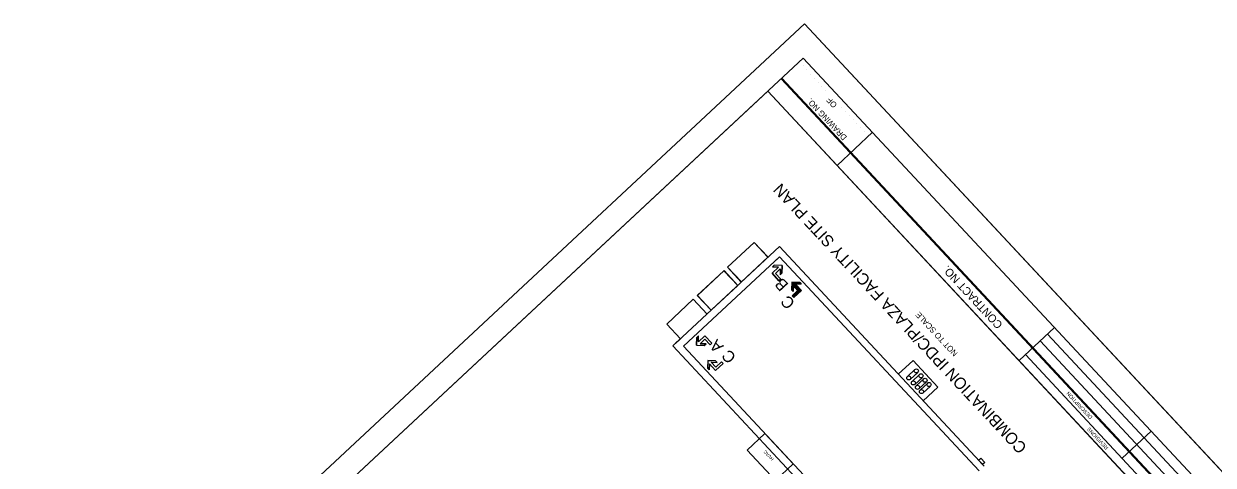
# Model space of a CAD drawing. Extents: x 1121979 to 1130574, y 1838676 to 1848573.
# Drawn here: x 1129608.35 to 1129657.38, y 1839397.19 to 1839415.39 of the extents above; entities that cross this region are included whole.
import ezdxf

# ---------------------------------------------------------------- set-up
doc = ezdxf.new("R2010")
doc.units = 0
for name, color, linetype in [('CLB-6', 7, 'Continuous'), ('Default', 7, 'Continuous'), ('Future by Others', 7, 'Continuous'), ('GE-NOT-Notes', 7, 'Continuous'), ('GE-NOT-Titles', 7, 'Continuous'), ('GE-SHT-Clip Border', 7, 'Continuous'), ('GE-SHT-General', 7, 'Continuous'), ('GE-SHT-Plot Border', 7, 'Continuous'), ('HS_Dimensions and Text', 7, 'Continuous'), ('IPDC BUILDING RELATED', 7, 'Continuous'), ('IPDC ELECT ITS RELATED', 7, 'Continuous'), ('IPDC-EXIST ELECT EQUIP', 7, 'Continuous'), ('IT-PCM-Proposed Communications Conduit', 7, 'Continuous'), ('Sheets_General Details', 7, 'Continuous'), ('Sheets_Printer Plotting Border', 7, 'Continuous')]:
    doc.layers.add(name, color=color, linetype=linetype)

msp = doc.modelspace()

# ---------------------------------------------------------------- linework, layer by layer
at = {"layer": 'CLB-6'}
for p, q in [((1129635.85, 1839401.766), (1129635.839, 1839401.777)), ((1129636.186, 1839401.406), (1129636.175, 1839401.417))]:
    msp.add_line(p, q, dxfattribs=at)
at = {"layer": 'Default'}
for p, q in [((1129635.22, 1839402.222), (1129635.389, 1839402.381)), ((1129635.223, 1839402.214), (1129635.395, 1839402.375)), ((1129635.389, 1839402.381), (1129635.395, 1839402.375))]:
    msp.add_line(p, q, dxfattribs=at)
at = {"layer": 'Future by Others'}
msp.add_lwpolyline([(1129647.873, 1839397.217), (1129647.703, 1839397.399), (1129647.794, 1839397.485), (1129647.964, 1839397.302)], close=True, dxfattribs=at)
at = {"layer": 'GE-NOT-Notes'}
for p, q in [((1129686.907, 1839365.651), (1129640.533, 1839415.386)), ((1129639.194, 1839405.101), (1129639.464, 1839405.353)), ((1129639.288, 1839405.43), (1129639.215, 1839405.362)), ((1129639.464, 1839405.353), (1129639.215, 1839405.362)), ((1129639.608, 1839405.419), (1129639.288, 1839405.43)), ((1129639.335, 1839405.096), (1129639.532, 1839405.28)), ((1129639.532, 1839405.28), (1129639.524, 1839405.031)), ((1129639.608, 1839405.419), (1129639.597, 1839405.1)), ((1129639.48, 1839404.794), (1129639.194, 1839405.101)), ((1129639.553, 1839404.862), (1129639.335, 1839405.096)), ((1129639.553, 1839404.862), (1129639.48, 1839404.794)), ((1129639.597, 1839405.1), (1129639.524, 1839405.031)), ((1129640.013, 1839404.737), (1129640.002, 1839404.417)), ((1129640.013, 1839404.737), (1129640.333, 1839404.726)), ((1129640.404, 1839404.391), (1129640.152, 1839404.661)), ((1129640.152, 1839404.661), (1129640.401, 1839404.652)), ((1129640.333, 1839404.726), (1129640.401, 1839404.652)), ((1129640.002, 1839404.417), (1129640.07, 1839404.344)), ((1129640.029, 1839404.178), (1129640.263, 1839404.396)), ((1129640.029, 1839404.178), (1129640.097, 1839404.104)), ((1129640.079, 1839404.593), (1129640.07, 1839404.344)), ((1129640.263, 1839404.396), (1129640.079, 1839404.593)), ((1129640.097, 1839404.104), (1129640.404, 1839404.391)), ((1129636.084, 1839402.133), (1129636.095, 1839402.453)), ((1129636.095, 1839402.453), (1129636.168, 1839402.521)), ((1129636.43, 1839402.524), (1129636.159, 1839402.272)), ((1129636.159, 1839402.272), (1129636.168, 1839402.521)), ((1129636.425, 1839402.383), (1129636.228, 1839402.199)), ((1129636.228, 1839402.199), (1129636.476, 1839402.19)), ((1129636.403, 1839402.122), (1129636.476, 1839402.19)), ((1129636.643, 1839402.149), (1129636.425, 1839402.383)), ((1129636.716, 1839402.217), (1129636.43, 1839402.524)), ((1129636.643, 1839402.149), (1129636.716, 1839402.217)), ((1129636.084, 1839402.133), (1129636.403, 1839402.122)), ((1129636.55, 1839401.508), (1129636.539, 1839401.188)), ((1129636.55, 1839401.508), (1129636.869, 1839401.496)), ((1129636.616, 1839401.364), (1129636.607, 1839401.115)), ((1129636.868, 1839401.093), (1129636.616, 1839401.364)), ((1129636.873, 1839401.235), (1129636.689, 1839401.432)), ((1129636.689, 1839401.432), (1129636.938, 1839401.423)), ((1129637.175, 1839401.38), (1129636.868, 1839401.093)), ((1129636.869, 1839401.496), (1129636.938, 1839401.423)), ((1129637.107, 1839401.453), (1129636.873, 1839401.235)), ((1129637.107, 1839401.453), (1129637.175, 1839401.38)), ((1129636.539, 1839401.188), (1129636.607, 1839401.115))]:
    msp.add_line(p, q, dxfattribs=at)
at = {"layer": 'GE-SHT-Clip Border'}
msp.add_lwpolyline([(1129652.729, 1839339.252), (1129609.766, 1839385.33), (1129639.021, 1839412.608), (1129681.985, 1839366.531)], close=True, dxfattribs=at)
msp.add_lwpolyline([(1129652.729, 1839339.252), (1129609.766, 1839385.33), (1129639.021, 1839412.608), (1129681.985, 1839366.531)], close=True, dxfattribs=at)
msp.add_lwpolyline([(1129652.729, 1839339.252), (1129609.766, 1839385.33), (1129639.021, 1839412.608), (1129681.985, 1839366.531)], close=True, dxfattribs=at)
at = {"layer": 'GE-SHT-General'}
for p, q in [((1129640.484, 1839413.972), (1129640.484, 1839413.972)), ((1129640.475, 1839413.647), (1129640.475, 1839413.647)), ((1129640.63, 1839413.481), (1129640.63, 1839413.481)), ((1129656.061, 1839395.434), (1129639.57, 1839413.12)), ((1129656.092, 1839395.463), (1129639.601, 1839413.149)), ((1129640.784, 1839413.315), (1129640.784, 1839413.315)), ((1129640.939, 1839413.149), (1129640.939, 1839413.149)), ((1129641.094, 1839412.984), (1129641.094, 1839412.984)), ((1129639.021, 1839412.608), (1129681.985, 1839366.531)), ((1129641.248, 1839412.818), (1129641.248, 1839412.818)), ((1129641.403, 1839412.652), (1129641.403, 1839412.652)), ((1129642.077, 1839411.929), (1129642.077, 1839411.929)), ((1129642.231, 1839411.764), (1129642.231, 1839411.764)), ((1129642.386, 1839411.598), (1129642.386, 1839411.598)), ((1129642.54, 1839411.432), (1129642.54, 1839411.432)), ((1129642.695, 1839411.266), (1129642.695, 1839411.266)), ((1129642.849, 1839411.101), (1129642.849, 1839411.101)), ((1129643.336, 1839410.914), (1129641.873, 1839409.55)), ((1129643.004, 1839410.935), (1129643.004, 1839410.935)), ((1129650.837, 1839402.869), (1129649.374, 1839401.505)), ((1129656.387, 1839395.738), (1129650.249, 1839402.321)), ((1129656.682, 1839396.013), (1129650.544, 1839402.596)), ((1129649.638, 1839401.75), (1129655.775, 1839395.168)), ((1129654.824, 1839398.593), (1129653.624, 1839397.475))]:
    msp.add_line(p, q, dxfattribs=at)
msp.add_lwpolyline([(1129652.729, 1839339.252), (1129609.766, 1839385.33), (1129640.484, 1839413.972), (1129683.448, 1839367.895)], close=True, dxfattribs=at)
at = {"layer": 'GE-SHT-Plot Border'}
msp.add_lwpolyline([(1129686.907, 1839365.651), (1129640.533, 1839415.386), (1129608.352, 1839385.379), (1129654.726, 1839335.645)], close=True, dxfattribs=at)
at = {"layer": 'IPDC BUILDING RELATED'}
for points in [[(1129639.497, 1839406.199), (1129635.108, 1839402.107)], [(1129639.497, 1839406.199), (1129647.94, 1839397.144)], [(1129639.507, 1839405.781), (1129635.548, 1839402.09)], [(1129639.507, 1839405.781), (1129639.231, 1839405.524)], [(1129647.737, 1839396.955), (1129639.507, 1839405.781)], [(1129635.108, 1839402.107), (1129648.066, 1839388.211), (1129652.454, 1839392.303), (1129652.117, 1839392.664)], [(1129652.084, 1839392.292), (1129648.126, 1839388.601), (1129635.548, 1839402.09)]]:
    msp.add_lwpolyline(points, dxfattribs=at)
msp.add_lwpolyline([(1129638.899, 1839398.497), (1129638.167, 1839397.815), (1129639.34, 1839396.558), (1129640.071, 1839397.24)], close=True, dxfattribs=at)
at = {"layer": 'IPDC ELECT ITS RELATED'}
for p, q in [((1129637.365, 1839405.352), (1129638.463, 1839406.375)), ((1129639.031, 1839405.765), (1129638.463, 1839406.375)), ((1129636.119, 1839404.189), (1129637.216, 1839405.212)), ((1129637.784, 1839404.603), (1129637.216, 1839405.212)), ((1129637.934, 1839404.742), (1129637.365, 1839405.352)), ((1129636.687, 1839403.58), (1129636.119, 1839404.189)), ((1129634.852, 1839403.008), (1129635.949, 1839404.031)), ((1129636.517, 1839403.421), (1129635.949, 1839404.031)), ((1129635.42, 1839402.398), (1129634.852, 1839403.008))]:
    msp.add_line(p, q, dxfattribs=at)
at = {"layer": 'IPDC-EXIST ELECT EQUIP'}
for p, q in [((1129638.457, 1839406.369), (1129637.36, 1839405.347)), ((1129639.026, 1839405.76), (1129638.457, 1839406.369)), ((1129639.026, 1839405.76), (1129637.928, 1839404.737)), ((1129637.211, 1839405.207), (1129636.113, 1839404.184)), ((1129637.779, 1839404.597), (1129637.211, 1839405.207)), ((1129637.928, 1839404.737), (1129637.36, 1839405.347)), ((1129636.682, 1839403.575), (1129636.113, 1839404.184)), ((1129637.779, 1839404.597), (1129636.682, 1839403.575)), ((1129644.396, 1839400.938), (1129645.005, 1839401.506)), ((1129646.028, 1839400.409), (1129645.005, 1839401.506)), ((1129645.419, 1839399.841), (1129646.028, 1839400.409))]:
    msp.add_line(p, q, dxfattribs=at)
at = {"layer": 'IT-PCM-Proposed Communications Conduit'}
for p, q in [((1129644.773, 1839400.847), (1129645.085, 1839401.138)), ((1129644.887, 1839400.725), (1129645.199, 1839401.016)), ((1129644.964, 1839400.643), (1129645.276, 1839400.934)), ((1129645.078, 1839400.52), (1129645.39, 1839400.811)), ((1129645.134, 1839400.46), (1129645.446, 1839400.752)), ((1129645.248, 1839400.338), (1129645.56, 1839400.629)), ((1129645.297, 1839400.285), (1129645.609, 1839400.576)), ((1129645.411, 1839400.163), (1129645.723, 1839400.454))]:
    msp.add_line(p, q, dxfattribs=at)
for centre in [(1129644.83, 1839400.786), (1129645.142, 1839401.077), (1129645.333, 1839400.873), (1129645.503, 1839400.69), (1129645.021, 1839400.582), (1129645.191, 1839400.399), (1129645.354, 1839400.224), (1129645.666, 1839400.515)]:
    msp.add_circle(centre, 0.0836, dxfattribs=at)
at = {"layer": 'Sheets_General Details'}
for p, q in [((1129639.464, 1839405.353), (1129639.194, 1839405.101)), ((1129639.288, 1839405.43), (1129639.215, 1839405.362)), ((1129639.215, 1839405.362), (1129639.464, 1839405.353)), ((1129639.608, 1839405.419), (1129639.288, 1839405.43)), ((1129639.335, 1839405.096), (1129639.532, 1839405.28)), ((1129639.532, 1839405.28), (1129639.524, 1839405.031)), ((1129639.597, 1839405.1), (1129639.608, 1839405.419)), ((1129639.194, 1839405.101), (1129639.48, 1839404.794)), ((1129639.553, 1839404.862), (1129639.335, 1839405.096)), ((1129639.48, 1839404.794), (1129639.553, 1839404.862)), ((1129639.524, 1839405.031), (1129639.597, 1839405.1)), ((1129640.013, 1839404.737), (1129640.002, 1839404.417)), ((1129640.188, 1839404.622), (1129640.009, 1839404.629)), ((1129640.159, 1839404.653), (1129640.01, 1839404.659)), ((1129640.169, 1839404.643), (1129640.01, 1839404.649)), ((1129640.178, 1839404.633), (1129640.01, 1839404.639)), ((1129640.379, 1839404.676), (1129640.011, 1839404.689)), ((1129640.389, 1839404.665), (1129640.011, 1839404.679)), ((1129640.398, 1839404.655), (1129640.011, 1839404.669)), ((1129640.35, 1839404.707), (1129640.012, 1839404.719)), ((1129640.36, 1839404.696), (1129640.012, 1839404.709)), ((1129640.369, 1839404.686), (1129640.012, 1839404.699)), ((1129640.333, 1839404.726), (1129640.013, 1839404.737)), ((1129640.341, 1839404.717), (1129640.013, 1839404.729)), ((1129640.404, 1839404.391), (1129640.152, 1839404.661)), ((1129640.152, 1839404.661), (1129640.401, 1839404.652)), ((1129640.401, 1839404.652), (1129640.333, 1839404.726)), ((1129640.073, 1839404.426), (1129640.002, 1839404.429)), ((1129640.073, 1839404.416), (1129640.002, 1839404.419)), ((1129640.002, 1839404.417), (1129640.07, 1839404.344)), ((1129640.074, 1839404.456), (1129640.003, 1839404.459)), ((1129640.074, 1839404.446), (1129640.003, 1839404.449)), ((1129640.073, 1839404.436), (1129640.003, 1839404.439)), ((1129640.075, 1839404.486), (1129640.004, 1839404.489)), ((1129640.075, 1839404.476), (1129640.004, 1839404.479)), ((1129640.074, 1839404.466), (1129640.004, 1839404.469)), ((1129640.076, 1839404.516), (1129640.005, 1839404.519)), ((1129640.076, 1839404.506), (1129640.005, 1839404.509)), ((1129640.075, 1839404.496), (1129640.005, 1839404.499)), ((1129640.077, 1839404.546), (1129640.006, 1839404.549)), ((1129640.077, 1839404.536), (1129640.006, 1839404.539)), ((1129640.076, 1839404.526), (1129640.006, 1839404.529)), ((1129640.078, 1839404.566), (1129640.007, 1839404.569)), ((1129640.077, 1839404.556), (1129640.007, 1839404.559)), ((1129640.217, 1839404.591), (1129640.008, 1839404.599)), ((1129640.079, 1839404.586), (1129640.008, 1839404.589)), ((1129640.078, 1839404.576), (1129640.008, 1839404.579)), ((1129640.198, 1839404.612), (1129640.009, 1839404.619)), ((1129640.207, 1839404.602), (1129640.009, 1839404.609)), ((1129640.072, 1839404.406), (1129640.01, 1839404.408)), ((1129640.072, 1839404.396), (1129640.02, 1839404.398)), ((1129640.263, 1839404.396), (1129640.029, 1839404.178)), ((1129640.072, 1839404.386), (1129640.029, 1839404.388)), ((1129640.029, 1839404.178), (1129640.097, 1839404.104)), ((1129640.17, 1839404.173), (1129640.029, 1839404.178)), ((1129640.16, 1839404.163), (1129640.038, 1839404.167)), ((1129640.071, 1839404.376), (1129640.039, 1839404.377)), ((1129640.181, 1839404.182), (1129640.039, 1839404.187)), ((1129640.15, 1839404.153), (1129640.048, 1839404.157)), ((1129640.071, 1839404.366), (1129640.049, 1839404.367)), ((1129640.191, 1839404.192), (1129640.05, 1839404.197)), ((1129640.071, 1839404.356), (1129640.058, 1839404.357)), ((1129640.139, 1839404.144), (1129640.058, 1839404.147)), ((1129640.201, 1839404.202), (1129640.06, 1839404.207)), ((1129640.129, 1839404.134), (1129640.067, 1839404.136)), ((1129640.07, 1839404.346), (1129640.068, 1839404.346)), ((1129640.07, 1839404.344), (1129640.079, 1839404.593)), ((1129640.212, 1839404.211), (1129640.07, 1839404.216)), ((1129640.079, 1839404.593), (1129640.263, 1839404.396)), ((1129640.222, 1839404.221), (1129640.081, 1839404.226)), ((1129640.227, 1839404.581), (1129640.085, 1839404.586)), ((1129640.232, 1839404.231), (1129640.091, 1839404.236)), ((1129640.236, 1839404.571), (1129640.095, 1839404.576)), ((1129640.097, 1839404.104), (1129640.404, 1839404.391)), ((1129640.243, 1839404.24), (1129640.101, 1839404.245)), ((1129640.246, 1839404.56), (1129640.105, 1839404.565)), ((1129640.253, 1839404.25), (1129640.112, 1839404.255)), ((1129640.256, 1839404.55), (1129640.114, 1839404.555)), ((1129640.263, 1839404.26), (1129640.122, 1839404.264)), ((1129640.265, 1839404.54), (1129640.124, 1839404.545)), ((1129640.274, 1839404.269), (1129640.132, 1839404.274)), ((1129640.275, 1839404.529), (1129640.134, 1839404.534)), ((1129640.285, 1839404.519), (1129640.143, 1839404.524)), ((1129640.284, 1839404.279), (1129640.143, 1839404.284)), ((1129640.294, 1839404.509), (1129640.153, 1839404.514)), ((1129640.294, 1839404.288), (1129640.153, 1839404.293)), ((1129640.304, 1839404.498), (1129640.162, 1839404.503)), ((1129640.305, 1839404.298), (1129640.163, 1839404.303)), ((1129640.313, 1839404.488), (1129640.172, 1839404.493)), ((1129640.315, 1839404.308), (1129640.174, 1839404.313)), ((1129640.323, 1839404.478), (1129640.182, 1839404.483)), ((1129640.325, 1839404.317), (1129640.184, 1839404.322)), ((1129640.333, 1839404.467), (1129640.191, 1839404.472)), ((1129640.336, 1839404.327), (1129640.194, 1839404.332)), ((1129640.342, 1839404.457), (1129640.201, 1839404.462)), ((1129640.346, 1839404.337), (1129640.205, 1839404.342)), ((1129640.352, 1839404.447), (1129640.211, 1839404.451)), ((1129640.356, 1839404.346), (1129640.215, 1839404.351)), ((1129640.362, 1839404.436), (1129640.22, 1839404.441)), ((1129640.367, 1839404.356), (1129640.225, 1839404.361)), ((1129640.371, 1839404.426), (1129640.23, 1839404.431)), ((1129640.377, 1839404.366), (1129640.236, 1839404.371)), ((1129640.381, 1839404.416), (1129640.24, 1839404.42)), ((1129640.388, 1839404.375), (1129640.246, 1839404.38)), ((1129640.391, 1839404.405), (1129640.249, 1839404.41)), ((1129640.398, 1839404.385), (1129640.257, 1839404.39)), ((1129640.4, 1839404.395), (1129640.259, 1839404.4)), ((1129640.119, 1839404.125), (1129640.077, 1839404.126)), ((1129640.108, 1839404.115), (1129640.087, 1839404.116)), ((1129640.098, 1839404.105), (1129640.096, 1839404.105)), ((1129636.095, 1839402.453), (1129636.084, 1839402.133)), ((1129636.168, 1839402.521), (1129636.095, 1839402.453)), ((1129636.43, 1839402.524), (1129636.159, 1839402.272)), ((1129636.159, 1839402.272), (1129636.168, 1839402.521)), ((1129636.228, 1839402.199), (1129636.425, 1839402.383)), ((1129636.476, 1839402.19), (1129636.228, 1839402.199)), ((1129636.403, 1839402.122), (1129636.476, 1839402.19)), ((1129636.425, 1839402.383), (1129636.643, 1839402.149)), ((1129636.716, 1839402.217), (1129636.43, 1839402.524)), ((1129636.643, 1839402.149), (1129636.716, 1839402.217)), ((1129636.084, 1839402.133), (1129636.403, 1839402.122)), ((1129636.55, 1839401.508), (1129636.539, 1839401.188)), ((1129636.869, 1839401.496), (1129636.55, 1839401.508)), ((1129636.607, 1839401.115), (1129636.616, 1839401.364)), ((1129636.616, 1839401.364), (1129636.868, 1839401.093)), ((1129636.873, 1839401.235), (1129636.689, 1839401.432)), ((1129636.689, 1839401.432), (1129636.938, 1839401.423)), ((1129636.868, 1839401.093), (1129637.175, 1839401.38)), ((1129636.938, 1839401.423), (1129636.869, 1839401.496)), ((1129637.107, 1839401.453), (1129636.873, 1839401.235)), ((1129637.175, 1839401.38), (1129637.107, 1839401.453)), ((1129636.539, 1839401.188), (1129636.607, 1839401.115))]:
    msp.add_line(p, q, dxfattribs=at)
at = {"layer": 'Sheets_Printer Plotting Border'}
msp.add_line((1129647.387, 1839397.33), (1129647.364, 1839397.308), dxfattribs=at)

# ---------------------------------------------------------------- texts
at = {"layer": 'GE-NOT-Notes'}
for s, p in [('B', (1129639.899, 1839404.64)), ('C', (1129640.172, 1839403.893)), ('A', (1129637.22, 1839402.097)), ('C', (1129637.744, 1839401.656))]:
    msp.add_text(s, height=0.48, rotation=132.9971, dxfattribs=at).set_placement(p)
at = {"layer": 'GE-NOT-Titles'}
msp.add_text('COMBINATION IPDC/PLAZA FACILITY SITE PLAN', height=0.48, rotation=132.9971, dxfattribs=at).set_placement((1129649.728, 1839397.941))
at = {"layer": 'GE-SHT-General'}
for s, height, rotation, p in [('DRAWING NO.', 0.24, 132.9972, (1129642.3, 1839410.72)), ('OF', 0.24, 132.9972, (1129641.894, 1839412.055)), ('CONTRACT NO.', 0.33, 132.9971, (1129648.722, 1839402.996)), ('DESCRIPTION', 0.15404, 132.9972, (1129652.414, 1839399.176)), ('REVISIONS', 0.154, 132.9972, (1129653.068, 1839397.918))]:
    msp.add_text(s, height=height, rotation=rotation, dxfattribs=at).set_placement(p)
at = {"layer": 'HS_Dimensions and Text'}
for s, height, p in [('NOT TO SCALE', 0.24, (1129646.868, 1839401.814)), ('HVAC', 0.1333, (1129639.277, 1839397.45))]:
    msp.add_text(s, height=height, rotation=132.9971, dxfattribs=at).set_placement(p)

doc.saveas('drawing.dxf')
